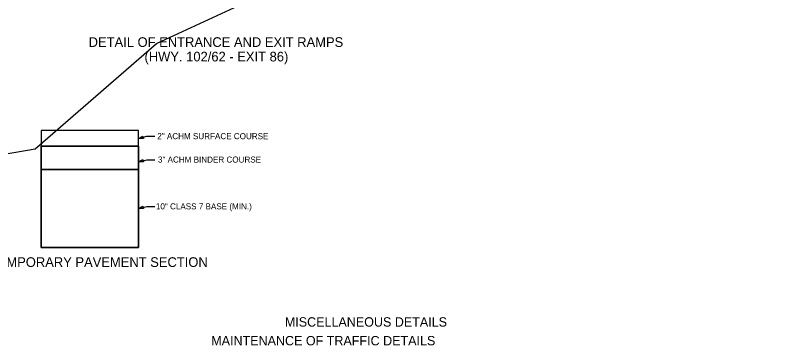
# Model space of a CAD drawing. Extents: x 1017892 to 1236694, y 658811 to 792468.
# Drawn here: x 1023342 to 1025330, y 658811 to 659657 of the extents above; entities that cross this region are included whole.
import ezdxf

# ---------------------------------------------------------------- set-up
doc = ezdxf.new("R2010")
doc.units = 0
for name, color, linetype in [('Default', 7, 'Continuous'), ('Level 8', 7, 'Continuous'), ('R_Border', 7, 'Continuous'), ('R_Proposed Road Annot', 7, 'Continuous'), ('S_EDGE_PAVEMENT', 7, 'Continuous')]:
    doc.layers.add(name, color=color, linetype=linetype)

msp = doc.modelspace()

# ---------------------------------------------------------------- linework, layer by layer
at = {"layer": 'R_Border'}
for points in [[(1023703.1, 659584.8), (1024091.7, 659765.6), (1025330.1, 660089.9)], [(1023102.3, 659265.6), (1023391.6, 659315.3), (1023703.1, 659584.8)]]:
    msp.add_lwpolyline(points, dxfattribs=at)
at = {"layer": 'R_Proposed Road Annot'}
for p, q in [((1023678.4, 659347.1), (1023698.8, 659347.1)), ((1023678.4, 659287.1), (1023698.8, 659287.1)), ((1023678.4, 659167.1), (1023698.8, 659167.1))]:
    msp.add_line(p, q, dxfattribs=at)
for points in [[(1023669.4, 659341.8), (1023657.1, 659341.8), (1023668, 659347.6)], [(1023407.1, 659321.8), (1023657.1, 659321.8), (1023657.1, 659261.8), (1023407.1, 659261.8)], [(1023669.4, 659281.8), (1023657.1, 659281.8), (1023668, 659287.6)], [(1023407.1, 659261.8), (1023657.1, 659261.8), (1023657.1, 659061.8), (1023407.1, 659061.8)], [(1023669.4, 659161.8), (1023657.1, 659161.8), (1023668, 659167.6)]]:
    msp.add_lwpolyline(points, close=True, dxfattribs=at)
for points in [[(1023657.1, 659341.8), (1023678.4, 659347.1)], [(1023657.1, 659281.8), (1023678.4, 659287.1)], [(1023657.1, 659161.8), (1023678.4, 659167.1)]]:
    msp.add_lwpolyline(points, dxfattribs=at)
at = {"layer": 'S_EDGE_PAVEMENT'}
for p, q in [((1023657.1, 659361.8), (1023407.1, 659361.8)), ((1023407.1, 659361.8), (1023407.1, 659321.8)), ((1023657.1, 659321.8), (1023657.1, 659361.8)), ((1023407.1, 659321.8), (1023407.1, 659241.8)), ((1023657.1, 659321.8), (1023407.1, 659321.8)), ((1023657.1, 659241.8), (1023657.1, 659321.8)), ((1023657.1, 659261.8), (1023407.1, 659261.8)), ((1023407.1, 659241.8), (1023407.1, 659061.8)), ((1023657.1, 659061.8), (1023657.1, 659241.8)), ((1023407.1, 659061.8), (1023657.1, 659061.8))]:
    msp.add_line(p, q, dxfattribs=at)

# ---------------------------------------------------------------- texts
at = {"layer": 'Default'}
for s, p in [('MISCELLANEOUS DETAILS', (1024031.8, 658859.2)), ('MAINTENANCE OF TRAFFIC DETAILS', (1023843.2, 658811.2))]:
    msp.add_text(s, height=24, rotation=360, dxfattribs=at).set_placement(p)
at = {"layer": 'Level 8'}
for s, p in [('DETAIL OF ENTRANCE AND EXIT RAMPS', (1023529.1, 659576.2)), ('(HWY. 102/62 - EXIT 86)', (1023672.1, 659539)), ('HWY. 72 TEMPORARY PAVEMENT SECTION', (1023134, 659012.2))]:
    msp.add_text(s, height=24.8, dxfattribs=at).set_placement(p)
at = {"layer": 'R_Proposed Road Annot'}
for s, p in [('2" ACHM SURFACE COURSE', (1023704.9, 659339.7)), ('3" ACHM BINDER COURSE', (1023706.7, 659279.7)), ('10" CLASS 7 BASE (MIN.)', (1023701.4, 659159.7))]:
    msp.add_text(s, height=15.5, dxfattribs=at).set_placement(p)

doc.saveas('drawing.dxf')
